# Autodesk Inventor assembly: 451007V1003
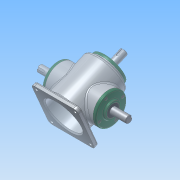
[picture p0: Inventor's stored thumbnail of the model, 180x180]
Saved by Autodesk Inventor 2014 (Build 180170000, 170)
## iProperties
Created: 2015-10
Part Number: 451007V1003
Document SubType Name: Assembly
Designer: net
Author: net
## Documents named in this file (14)
- C:\Users\net\Desktop\451007V1003\답안조립품.iam
- C:\Users\net\Desktop\451007V1003\본체.ipt
- C:\Users\net\Desktop\451007V1003\서브 베벨기어.ipt
- C:\Users\net\Desktop\451007V1003\서브 축.ipt
- 서브 축.ipt
- C:\Users\net\Desktop\451007V1003\키 4x4.ipt
- C:\Users\net\Desktop\451007V1003\메인 베벨기어.ipt
- C:\Users\net\Desktop\451007V1003\메인 축.ipt
- 메인 축.ipt
- C:\Users\net\Desktop\451007V1003\키 5x5.ipt
- C:\Users\net\Desktop\451007V1003\베어링 6203.ipt
- C:\Users\net\Desktop\451007V1003\오일실.ipt
- C:\Users\net\Desktop\451007V1003\커버.ipt
- C:\Users\net\Desktop\451007V1003\M4.ipt
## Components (12 placed, 1 different names)
1. M4:2
2. M4:4
3. M4:5
4. M4:6
5. M4:3
6. M4:7
7. M4:8
8. M4:9
9. M4:1
10. M4:10
11. M4:11
12. M4:12
## Named parameters: d33_d22 = 0, d34_d31 = 0, d35_d32 = 0, d36_d2 = 0, d37_d3 = 0, d38_d4 = 0, d39_d5 = 0, d40_d6 = 0, d41_d19 = 0, d42_d20 = 0, d43_d21 = 0, d44_d0 = 0, d75_d72 = 0, d77_d59_d51 = 0
